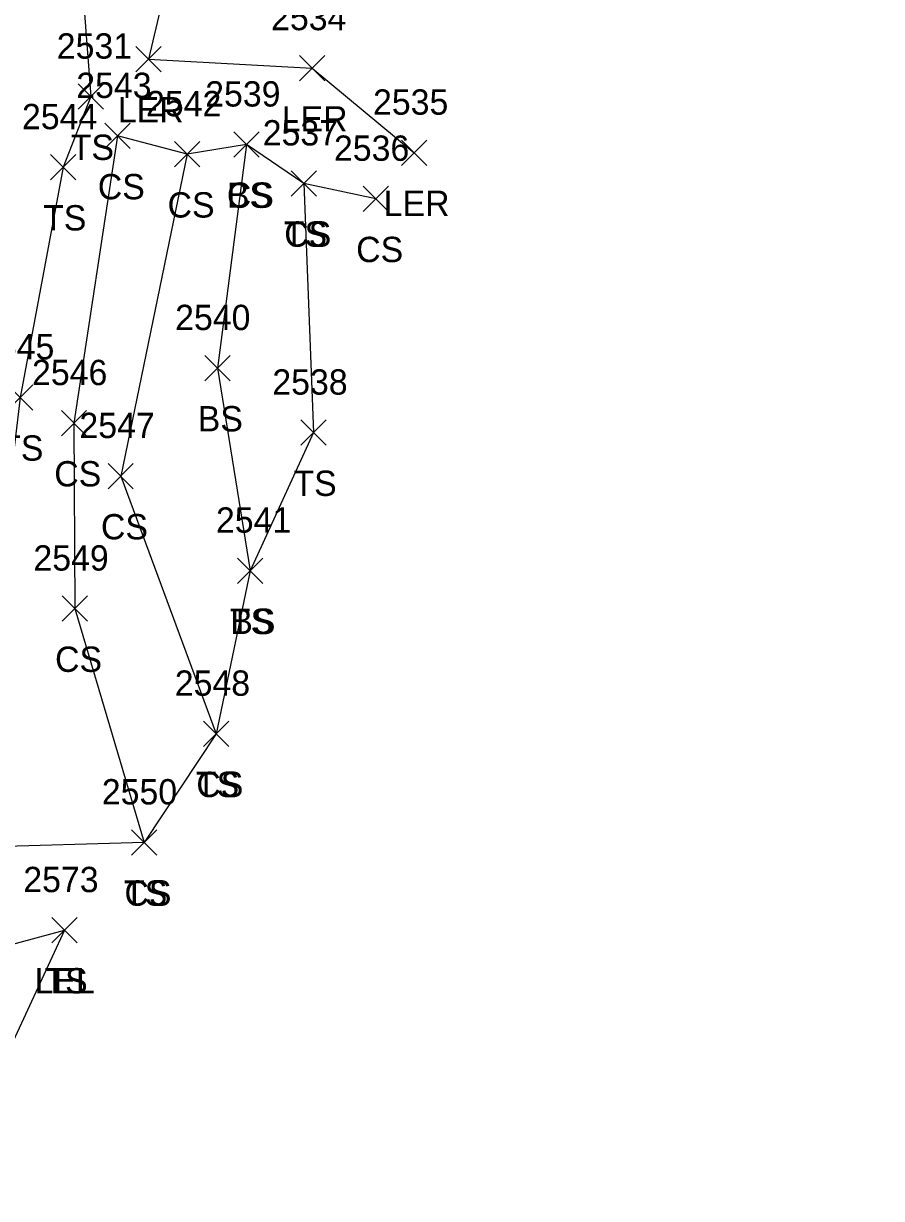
# Model space of a CAD drawing. Extents: x 1483143 to 1488182, y 802902 to 807581.
# Drawn here: x 1487772.4 to 1487840.2, y 805881.7 to 805974.5 of the extents above; entities that cross this region are included whole.
import ezdxf

# ---------------------------------------------------------------- set-up
doc = ezdxf.new("R2010")
doc.units = 0
for name, color, linetype in [('L_A', 7, 'Continuous'), ('L_I', 7, 'Continuous'), ('L_TIC', 7, 'Continuous'), ('LARO', 7, 'Continuous'), ('LELB', 7, 'Continuous')]:
    doc.layers.add(name, color=color, linetype=linetype)

msp = doc.modelspace()

# ---------------------------------------------------------------- linework, layer by layer
at = {"layer": 'L_TIC'}
for points in [[(1487781.271, 805970.685), (1487783.271, 805972.685)], [(1487783.271, 805970.685), (1487781.271, 805972.685)], [(1487794.219, 805969.967), (1487796.219, 805971.967)], [(1487796.219, 805969.967), (1487794.219, 805971.967)], [(1487776.725, 805967.72), (1487778.725, 805969.72)], [(1487778.725, 805967.72), (1487776.725, 805969.72)], [(1487778.831, 805964.612), (1487780.831, 805966.612)], [(1487780.831, 805964.612), (1487778.831, 805966.612)], [(1487789.024, 805963.938), (1487791.024, 805965.938)], [(1487791.024, 805963.938), (1487789.024, 805965.938)], [(1487789.024, 805963.938), (1487791.024, 805965.938)], [(1487791.024, 805963.938), (1487789.024, 805965.938)], [(1487802.273, 805963.293), (1487804.273, 805965.293)], [(1487804.273, 805963.293), (1487802.273, 805965.293)], [(1487784.341, 805963.17), (1487786.341, 805965.17)], [(1487786.341, 805963.17), (1487784.341, 805965.17)], [(1487784.341, 805963.17), (1487786.341, 805965.17)], [(1487786.341, 805963.17), (1487784.341, 805965.17)], [(1487774.54, 805962.149), (1487776.54, 805964.149)], [(1487776.54, 805962.149), (1487774.54, 805964.149)], [(1487793.559, 805960.863), (1487795.559, 805962.863)], [(1487795.559, 805960.863), (1487793.559, 805962.863)], [(1487793.559, 805960.863), (1487795.559, 805962.863)], [(1487795.559, 805960.863), (1487793.559, 805962.863)], [(1487799.242, 805959.651), (1487801.242, 805961.651)], [(1487801.242, 805959.651), (1487799.242, 805961.651)], [(1487786.726, 805946.281), (1487788.726, 805948.281)], [(1487788.726, 805946.281), (1487786.726, 805948.281)], [(1487771.15, 805943.968), (1487773.15, 805945.968)], [(1487773.15, 805943.968), (1487771.15, 805945.968)], [(1487775.392, 805941.934), (1487777.392, 805943.934)], [(1487777.392, 805941.934), (1487775.392, 805943.934)], [(1487794.319, 805941.184), (1487796.319, 805943.184)], [(1487796.319, 805941.184), (1487794.319, 805943.184)], [(1487779.079, 805937.752), (1487781.079, 805939.752)], [(1487781.079, 805937.752), (1487779.079, 805939.752)], [(1487789.297, 805930.28), (1487791.297, 805932.28)], [(1487791.297, 805930.28), (1487789.297, 805932.28)], [(1487789.297, 805930.28), (1487791.297, 805932.28)], [(1487791.297, 805930.28), (1487789.297, 805932.28)], [(1487775.454, 805927.288), (1487777.454, 805929.288)], [(1487777.454, 805927.288), (1487775.454, 805929.288)], [(1487786.614, 805917.4), (1487788.614, 805919.4)], [(1487788.614, 805917.4), (1487786.614, 805919.4)], [(1487786.614, 805917.4), (1487788.614, 805919.4)], [(1487788.614, 805917.4), (1487786.614, 805919.4)], [(1487780.935, 805908.819), (1487782.935, 805910.819)], [(1487782.935, 805908.819), (1487780.935, 805910.819)], [(1487780.935, 805908.819), (1487782.935, 805910.819)], [(1487782.935, 805908.819), (1487780.935, 805910.819)], [(1487774.645, 805901.891), (1487776.645, 805903.891)], [(1487776.645, 805901.891), (1487774.645, 805903.891)], [(1487774.645, 805901.891), (1487776.645, 805903.891)], [(1487776.645, 805901.891), (1487774.645, 805903.891)]]:
    msp.add_lwpolyline(points, dxfattribs=at)
at = {"layer": 'LARO'}
for points in [[(1487840.183, 806185.419), (1487834.667, 806182.603), (1487822.583, 806178.248), (1487811.013, 806152.676), (1487805.799, 806138.734), (1487805.568, 806125.086), (1487812.671, 806122.392), (1487808.756, 806106.514), (1487799.943, 806095.078), (1487791.747, 806069.314), (1487789.156, 806039.667), (1487787.774, 806021.847), (1487782.395, 806010.381), (1487772.438, 806000.496), (1487764.138, 805988.073), (1487767.263, 805965.452), (1487765.996, 805943.659), (1487763.649, 805933.944), (1487758.685, 805910.296), (1487765.404, 805900.116), (1487775.645, 805902.891)], [(1487840.183, 806185.419), (1487835.66, 806164.951), (1487831.662, 806144.041), (1487829.899, 806129.517), (1487831.501, 806094.601), (1487833.186, 806067.231), (1487831.828, 806052.009), (1487826.747, 806039.702), (1487819.717, 806036.653), (1487826.167, 806020.885), (1487825.98, 806002.413), (1487822.097, 805985.51), (1487816.733, 805985.65), (1487813.101, 806007.476), (1487813.044, 806016.36), (1487804.677, 806014.339), (1487795.815, 805998.555), (1487803.821, 805982.396), (1487790.915, 805980.553), (1487784.686, 805981.844), (1487782.271, 805971.685), (1487795.219, 805970.967), (1487803.273, 805964.293)]]:
    msp.add_lwpolyline(points, dxfattribs=at)
at = {"layer": 'LELB'}
for points in [[(1487791.747, 806069.314), (1487800.504, 806057.873), (1487800.388, 806042.543), (1487800.476, 806025.157), (1487789.316, 806004.691), (1487784.565, 805996.75), (1487778.772, 805994.848), (1487776.595, 805983.589), (1487777.725, 805968.72), (1487775.54, 805963.149), (1487772.15, 805944.968), (1487769.834, 805925.791)], [(1487785.341, 805964.17), (1487779.831, 805965.612), (1487776.392, 805942.934), (1487776.454, 805928.288), (1487781.935, 805909.819)], [(1487800.242, 805960.651), (1487794.559, 805961.863), (1487790.024, 805964.938), (1487785.341, 805964.17), (1487780.079, 805938.752), (1487787.614, 805918.4)], [(1487790.024, 805964.938), (1487787.726, 805947.281), (1487790.297, 805931.28)], [(1487794.559, 805961.863), (1487795.319, 805942.184), (1487790.297, 805931.28), (1487787.614, 805918.4), (1487781.935, 805909.819), (1487769.143, 805909.45), (1487769.834, 805925.791)], [(1487775.645, 805902.891), (1487768.803, 805888.134), (1487760.167, 805881.696)]]:
    msp.add_lwpolyline(points, dxfattribs=at)

# ---------------------------------------------------------------- texts
at = {"layer": 'L_A'}
for s, p in [('LER', (1487779.854, 805966.685)), ('LER', (1487792.802, 805965.967)), ('TS', (1487776.135, 805963.72)), ('CS', (1487778.272, 805960.612)), ('CS', (1487788.465, 805959.938)), ('BS', (1487788.465, 805959.938)), ('CS', (1487783.782, 805959.17)), ('CS', (1487783.782, 805959.17)), ('LER', (1487800.856, 805959.293)), ('TS', (1487773.95, 805958.149)), ('TS', (1487792.969, 805956.863)), ('CS', (1487793, 805956.863)), ('CS', (1487798.683, 805955.651)), ('BS', (1487786.167, 805942.281)), ('TS', (1487770.559, 805939.968)), ('CS', (1487774.832, 805937.934)), ('TS', (1487793.728, 805937.184)), ('CS', (1487778.52, 805933.752)), ('TS', (1487788.707, 805926.28)), ('BS', (1487788.738, 805926.28)), ('CS', (1487774.895, 805923.288)), ('TS', (1487786.023, 805913.4)), ('CS', (1487786.055, 805913.4)), ('TS', (1487780.345, 805904.819)), ('CS', (1487780.376, 805904.819)), ('LEL', (1487773.283, 805897.891)), ('TS', (1487774.055, 805897.891))]:
    msp.add_text(s, height=2, dxfattribs=at).set_placement(p)
at = {"layer": 'L_I'}
for s, p in [('2534', (1487791.96, 805973.967)), ('2531', (1487775.032, 805971.72)), ('2543', (1487776.571, 805968.612)), ('2539', (1487786.756, 805967.938)), ('2539', (1487786.756, 805967.938)), ('2542', (1487782.081, 805967.17)), ('2542', (1487782.081, 805967.17)), ('2535', (1487800.013, 805967.293)), ('2544', (1487772.281, 805966.149)), ('2537', (1487791.3, 805964.863)), ('2537', (1487791.3, 805964.863)), ('2536', (1487796.927, 805963.651)), ('2540', (1487784.38, 805950.281)), ('2545', (1487768.89, 805947.968)), ('2546', (1487773.077, 805945.934)), ('2538', (1487792.059, 805945.184)), ('2547', (1487776.819, 805941.752)), ('2541', (1487787.605, 805934.28)), ('2541', (1487787.605, 805934.28)), ('2549', (1487773.186, 805931.288)), ('2548', (1487784.354, 805921.4)), ('2548', (1487784.354, 805921.4)), ('2550', (1487778.589, 805912.819)), ('2550', (1487778.589, 805912.819)), ('2573', (1487772.386, 805905.891)), ('2573', (1487772.386, 805905.891))]:
    msp.add_text(s, height=2, dxfattribs=at).set_placement(p)

doc.saveas('drawing.dxf')
